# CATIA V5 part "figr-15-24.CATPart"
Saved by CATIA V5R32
Part number: Part1
Bounding box of the stored display mesh (mm): x -50 to 50, y -25 to 25, z -24 to 1
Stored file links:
  D:\PROJECTS\Project 2022\CATIA V5 6R 2022\Resources\Part Files\c15_catia_v5_6r2022_prt\figr-15-24.CATPart
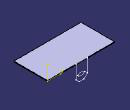
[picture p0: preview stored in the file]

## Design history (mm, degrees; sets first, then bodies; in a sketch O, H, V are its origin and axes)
SheetMetalParameters1: Thickness 1, BendRadius 2, KFactor 0.400515 {= log(min(100,max(20*SheetMetalParameters1.BendRadius,SheetMetalParameters1.Thickness)/SheetMetalParameters1.Thickness))/log(100)/2}, ReliefRadialLength 1, ReliefAxialLength 2, MinimumBendRadius 0
Body1 (main body)
  Sketch1 on xy-plane, origin (0, 0, 0), H (1, 0, 0), V (0, 1, 0)
    line L1 (-50, 25) -> (50, 25)
    line L2 (50, 25) -> (50, -25)
    line L3 (50, -25) -> (-50, -25)
    line L4 (-50, -25) -> (-50, 25)
    length L1 = 100
    distance V L2 = 50
    length L2 = 50
    distance H L3 = 25
    horizontal: L1 H, L3 H
    vertical: L2 V, L4 V
  Wall1: Thickness 1, Profile Sketch1
  Sketch2 on face of Wall1, origin (50, 25, 0), H (-1, 0, 0), V (0, 0, 1)
    line L1 (42.3549, 1) -> (42.3549, -19)
    point P2 (42.3549, -19)
    line L2 (42.3549, -19) -> (47.3549, -24)
    point P3 (47.3549, -24)
    line L3 (47.3549, -24) -> (54.3549, -24)
    point P4 (54.3549, -24)
    line L4 (54.3549, -24) -> (59.3549, -19)
    point P5 (59.3549, -19)
    line L5 (59.3549, -19) -> (59.3549, 1)
    line L6 (59.3549, 1) -> (42.3549, 1)
    reference projected line E1 (100, 1) -> (0, 1) from edge [face of Wall1 | face of Wall1]
    ellipse A1 centre (50.1164, -15.2153) semi-axes 5.0583, 2.1402 rotation 0
    length L5 = 20
    length L1 = 20
    length L3 = 7
    distance P4 L5 = 5
    distance P2 P3 H = 5
    distance L3 P5 = 5
    vertical: L1 V, L5 V
    horizontal: L3 H, L6 H
    coincidence: L6 E1
    parallelism: A1 L3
